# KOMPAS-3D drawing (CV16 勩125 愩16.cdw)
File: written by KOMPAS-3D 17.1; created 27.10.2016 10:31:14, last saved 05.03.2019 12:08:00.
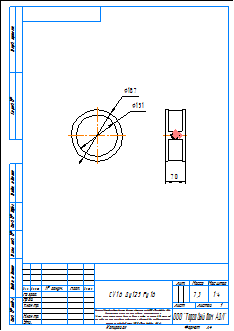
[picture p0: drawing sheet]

Sheet 1: A4, portrait

Title block, sheet 1: name: CV16 Ду125 Ру16; material: Сталь 20  ГОСТ 1050-88; mass: 7,3; sheets: 1; sheet format: A4; stored path: \\adlc.lan\data\АДЛ_ПКД\3D-модели\ADL production\Клапаны обратные ГРАНЛОК\CV16\KOMPAS 2D\CV16 Ду125 Ру16.cdw

Views: Вид 1, Проекционный вид 2
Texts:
  Klimkovich
  ADL
  Рама для чертежей
  Лит-Масса-Масштаб
  Материал-Предприятие
  Масштаб
  Изм.
  Лист
  № докум.
  Подп.
  Дата
  Лит.
  Разраб.
  Пров.
  Т.контр.
  Листов
  Внимание! Данный продукт является объектом авторского права ООО «Торговый Дом АДЛ».
  Запрещается изменение, копирование, распространение
  (в том числе путем копирования на другие сайты и ресурсы в Интернете)
  или любое иное использование информации и объектов без предварительного
  согласия правообладателя (ООО «Торговый Дом АДЛ»).
  Н.контр.
  Утв.
  ООО "Торговый дом АДЛ"
  Изменение
  Номер документа
  Подпись
  Обозначение документа
  Наименование изделия
  Масса изделия по ГОСТ 2.109-73
  Порядковый номер листа
  Общее количество листов в документе
  Характер работы, выполненной лицом, подписавшим документ
  Наименование или индекс предприятия, выпускающего документ
  Инв. № подл.
  Подп. и дата
  Взам. инв. №
  Инв. № дубл.
  Инвентарный номер подлинника по ГОСТ 2.501-68
  Подпись принявшего подлинник в отдел технической документации
  Инвентарный номер подлинника, взамен которого выпущен данный подлинник
  Инвентарный номер дубликата по ГОСТ 2.502-68
  Подпись принявшего дубликат в отдел технической документации
  Справ. №
  Перв. примен.
  Обозначение документа, взамен или на основании которого выпущен данный документ
  Обозначение документа, в котором впервые записан данный документ
  Подпись лица, копировавшего чертеж
  Обозначение формата листа
  !Рама для чертежа
Dimensions and other numbers on the sheet: 187; 151; 70; 1:4; 1; 7,3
